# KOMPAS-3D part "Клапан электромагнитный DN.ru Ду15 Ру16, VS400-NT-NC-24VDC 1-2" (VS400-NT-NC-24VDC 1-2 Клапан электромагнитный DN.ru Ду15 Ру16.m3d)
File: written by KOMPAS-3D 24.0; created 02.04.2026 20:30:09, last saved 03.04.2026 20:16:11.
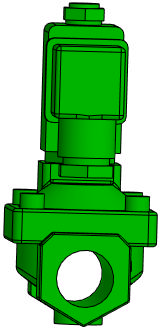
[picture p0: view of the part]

Document properties: Автор: artio; Полное имя файла: C:\Users\artio\OneDrive\Рабочий стол\Клапан электромагнитный DN.ru\VS400-NT-NC\VS400-NT-NC-24VDC 1-2 Клапан электромагнитный DN.ru Ду15 Ру16.m3d

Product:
- Body: Тело 1  | qty 1
    Масса: 1.030062
- Part/product: Клапан электромагнитный DN.ru Ду15 Ру16  | designation VS400-NT-NC-24VDC 1-2
    Масса: 0.759
    Раздел спецификации: Прочие изделия
    Примечание: D130-04726
    additional columns: ef56311e-7521-43dc-8291-0e6108b3d81d; VS400-ET-NC-220VAC 1-2; artio; c; Шероховатость не задана; Да

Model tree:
1. Операция без истории:1

Expressions: VS400-NT-NC-24VDC 1-2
